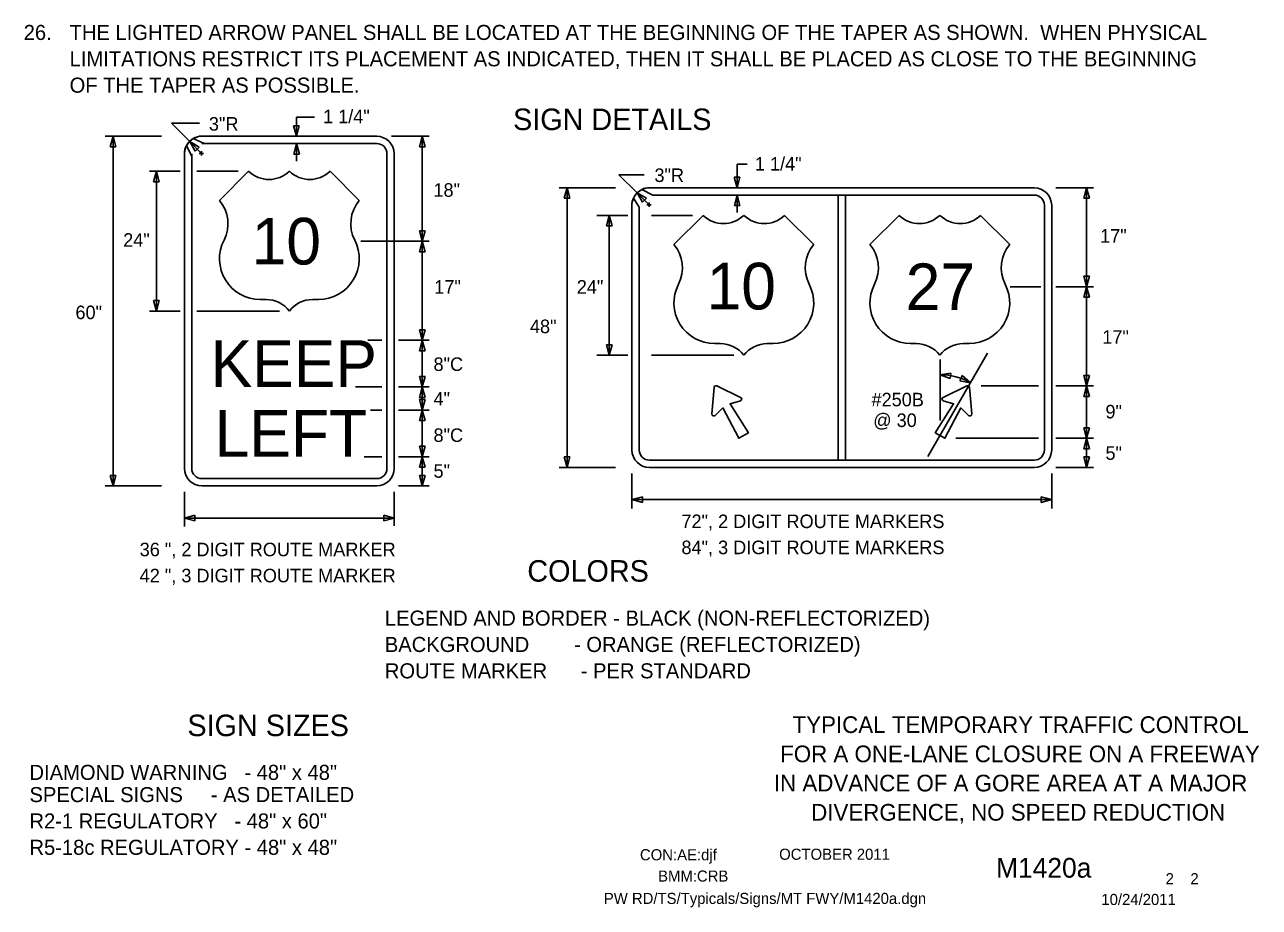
# Model space of a CAD drawing. Extents: x 16562 to 18475, y 6979 to 8243.
# Drawn here: x 17777 to 18465, y 7218 to 7710 of the extents above; entities that cross this region are included whole.
import ezdxf

# ---------------------------------------------------------------- set-up
doc = ezdxf.new("R2010")
doc.units = 0
for name, color, linetype in [('BORDER', 7, 'Continuous'), ('BORDER_SIGNAL_WO', 7, 'Continuous'), ('TRAFFIC_SIGNS_PR', 7, 'Continuous'), ('TYPICAL_EX', 7, 'Continuous'), ('TYPICAL_TEXT_DIMEN_PR', 7, 'Continuous')]:
    doc.layers.add(name, color=color, linetype=linetype)

msp = doc.modelspace()

# ---------------------------------------------------------------- linework, layer by layer
at = {"layer": 'TRAFFIC_SIGNS_PR'}
for p, q in [((17875.46, 7648.14), (17972.96, 7648.14)), ((17867.88, 7644.52), (17866.88, 7643.02)), ((17866.9, 7642.95), (17869.77, 7636.91)), ((17876.67, 7644.08), (17870.57, 7646.83)), ((17972.96, 7644.08), (17875.46, 7644.08)), ((17865.71, 7462.89), (17865.71, 7638.39)), ((17869.77, 7638.39), (17869.77, 7462.89)), ((17978.65, 7462.89), (17978.65, 7638.39)), ((17982.71, 7638.39), (17982.71, 7462.89)), ((18116.15, 7613.7), (18119.29, 7608.66)), ((18126.94, 7615.39), (18120.7, 7618.41)), ((18124.98, 7619.44), (18339.48, 7619.44)), ((18124.98, 7619.44), (18339.48, 7619.44)), ((18126.92, 7615.38), (18230.2, 7615.38)), ((18339.48, 7615.38), (18126.92, 7615.38)), ((18230.2, 7615.38), (18230.2, 7467.51)), ((18234.26, 7615.38), (18234.26, 7467.51)), ((18234.26, 7615.38), (18339.48, 7615.38)), ((18115.23, 7609.69), (18115.23, 7473.19)), ((18115.23, 7473.19), (18115.23, 7609.69)), ((18119.3, 7608.65), (18119.3, 7473.19)), ((18119.3, 7608.64), (18119.3, 7473.19)), ((18345.17, 7609.69), (18345.17, 7563.94)), ((18345.17, 7473.19), (18345.17, 7609.69)), ((18349.23, 7609.69), (18349.23, 7473.19)), ((18349.23, 7609.69), (18349.23, 7473.19)), ((18345.17, 7563.94), (18345.17, 7473.19)), ((18159.84, 7493.31), (18160.99, 7508.02)), ((18162.5, 7508.89), (18175.81, 7502.53)), ((18301.97, 7508.89), (18288.65, 7502.53)), ((18304.63, 7493.31), (18303.48, 7508.02)), ((18124.98, 7467.51), (18339.48, 7467.51)), ((18124.98, 7463.44), (18339.48, 7463.44)), ((18339.48, 7463.44), (18124.98, 7463.44)), ((17875.46, 7457.2), (17972.96, 7457.2)), ((17972.96, 7453.14), (17875.46, 7453.14))]:
    msp.add_line(p, q, dxfattribs=at)
for points in [[(18126.92, 7615.38), (18126.91, 7615.39)], [(18119.29, 7608.66), (18119.3, 7608.64)], [(18175.65, 7500.56), (18169.93, 7498.98), (18180.15, 7482.81), (18174.75, 7479.69), (18165.85, 7496.63), (18161.63, 7492.46)], [(18288.82, 7500.56), (18294.54, 7498.98), (18284.32, 7482.81), (18289.72, 7479.69), (18298.61, 7496.63), (18302.84, 7492.46)]]:
    msp.add_lwpolyline(points, dxfattribs=at)
msp.add_lwpolyline([(18230.2, 7615.38), (18234.26, 7615.38), (18234.26, 7467.51), (18230.2, 7467.51)], close=True, dxfattribs=at)
for centre, radius, start, end in [((17875.46, 7638.39), 9.75, 90, 180), ((17874.88, 7640.57), 7.6, 85.58319, 124.53531), ((17972.96, 7638.39), 9.75, 0, 90), ((17872.74, 7638.99), 7.06, 145.86811, 184.82317), ((17876.06, 7648.51), 4.47, 262.2432, 277.7568), ((17972.96, 7638.39), 5.69, 0, 90), ((17864.32, 7637.65), 5.51, 352.24294, 7.75653), ((18121.36, 7610.4), 6.17, 147.60925, 186.56283), ((18124.98, 7609.69), 9.75, 90, 180), ((18124.98, 7609.69), 9.75, 90, 180), ((18124.31, 7612.88), 6.6, 84.11162, 123.06374), ((18125.92, 7622.56), 7.24, 277.81035, 278.05403), ((18339.48, 7609.69), 9.75, 0, 90), ((18339.48, 7609.69), 9.75, 0, 90), ((18339.48, 7609.69), 5.69, 0, 89.99421), ((18339.48, 7609.69), 5.69, 0, 90), ((18162.04, 7507.94), 1.06, 64.48226, 175.51774), ((18302.42, 7507.94), 1.06, 4.48226, 115.51774), ((18175.36, 7501.58), 1.06, 285.9885, 64.48226), ((18289.11, 7501.58), 1.06, 115.51774, 254.0115), ((18160.89, 7493.22), 1.06, 175.51775, 314.01151), ((18303.58, 7493.22), 1.06, 225.98849, 4.48225), ((18124.98, 7473.19), 9.75, 180, 270), ((18124.98, 7473.19), 9.75, 180, 270), ((18124.98, 7473.19), 5.69, 180, 270), ((18124.98, 7473.19), 5.69, 180, 270), ((18339.48, 7473.19), 9.75, 270, 0), ((18339.48, 7473.19), 5.69, 270, 0), ((18339.48, 7473.19), 9.75, 270, 0), ((18339.48, 7473.19), 5.69, 270, 0), ((17875.46, 7462.89), 9.75, 180, 270), ((17875.46, 7462.89), 5.69, 180, 270), ((17972.96, 7462.89), 5.69, 270, 0), ((17972.96, 7462.89), 9.75, 270, 0)]:
    msp.add_arc(centre, radius, start, end, dxfattribs=at)
at = {"layer": 'TYPICAL_EX'}
for p, q in [((17885.21, 7612.4), (17901.46, 7628.65)), ((17963.21, 7612.4), (17946.96, 7628.65)), ((18138.59, 7587.79), (18154.84, 7604.04)), ((18216.6, 7587.79), (18200.34, 7604.04)), ((18247.87, 7587.79), (18264.12, 7604.04)), ((18325.88, 7587.79), (18309.62, 7604.04)), ((17907.94, 7557.1), (17911.19, 7557.1)), ((17940.48, 7557.1), (17937.23, 7557.1)), ((18161.32, 7532.49), (18164.57, 7532.49)), ((18193.87, 7532.49), (18190.62, 7532.49)), ((18270.6, 7532.49), (18273.85, 7532.49)), ((18303.15, 7532.49), (18299.9, 7532.49))]:
    msp.add_line(p, q, dxfattribs=at)
for centre, radius, start, end in [((17912.84, 7640.48), 16.42, 226.14041, 313.85958), ((17935.59, 7640.48), 16.42, 226.14042, 313.85959), ((17869.81, 7599.38), 20.16, 333.09768, 40.19361), ((17978.61, 7599.38), 20.16, 139.80639, 206.90233), ((18166.22, 7615.87), 16.42, 226.14041, 313.85958), ((18188.97, 7615.87), 16.42, 226.14042, 313.85959), ((18275.5, 7615.87), 16.42, 226.14041, 313.85958), ((18298.25, 7615.87), 16.42, 226.14042, 313.85959), ((17907.98, 7579.83), 22.73, 152.6698, 269.90132), ((17940.44, 7579.83), 22.73, 270.09868, 27.3302), ((18123.19, 7574.77), 20.16, 333.09768, 40.19361), ((18232, 7574.77), 20.16, 139.80639, 206.90233), ((18232.47, 7574.77), 20.16, 333.09768, 40.19361), ((18341.27, 7574.77), 20.16, 139.80639, 206.90233), ((18161.36, 7555.22), 22.73, 152.6698, 269.90132), ((18193.83, 7555.22), 22.73, 270.09868, 27.3302), ((18270.64, 7555.22), 22.73, 152.6698, 269.90132), ((18303.1, 7555.22), 22.73, 270.09868, 27.3302), ((17911.23, 7540.82), 16.28, 37.1038, 90.13853), ((17937.19, 7540.82), 16.28, 89.86147, 142.8962), ((18164.61, 7516.21), 16.28, 37.1038, 90.13853), ((18190.58, 7516.21), 16.28, 89.86147, 142.8962), ((18273.89, 7516.21), 16.28, 37.1038, 90.13853), ((18299.85, 7516.21), 16.28, 89.86147, 142.8962)]:
    msp.add_arc(centre, radius, start, end, dxfattribs=at)
at = {"layer": 'TYPICAL_TEXT_DIMEN_PR'}
for p, q in [((17874.08, 7655.43), (17858.42, 7655.43)), ((17858.42, 7655.43), (17868.66, 7645.19)), ((17928.18, 7658.9), (17928.18, 7648.14)), ((17928.18, 7658.9), (17938.29, 7658.9)), ((17852.88, 7648.14), (17821.59, 7648.14)), ((17824.35, 7642.28), (17825.93, 7648.14)), ((17825.93, 7648.14), (17825.93, 7453.14)), ((17825.93, 7648.14), (17827.5, 7642.28)), ((17928.18, 7648.14), (17926.61, 7654)), ((17926.61, 7654), (17928.18, 7654)), ((17928.18, 7654), (17929.75, 7654)), ((17929.75, 7654), (17928.18, 7648.14)), ((17981.25, 7648.14), (18002.21, 7648.14)), ((17996.74, 7642.28), (17998.31, 7648.14)), ((17998.31, 7648.14), (17998.31, 7589.64)), ((17998.31, 7648.14), (17999.89, 7642.28)), ((17825.93, 7642.28), (17824.35, 7642.28)), ((17827.5, 7642.28), (17825.93, 7642.28)), ((17868.66, 7645.19), (17875.22, 7638.63)), ((17871.7, 7639.94), (17868.66, 7645.19)), ((17868.66, 7645.19), (17873.92, 7642.16)), ((17872.81, 7641.05), (17871.7, 7639.94)), ((17873.92, 7642.16), (17872.81, 7641.05)), ((17926.66, 7638.22), (17928.23, 7644.08)), ((17928.23, 7644.08), (17928.23, 7634.33)), ((17928.23, 7644.08), (17929.8, 7638.22)), ((17998.31, 7642.28), (17996.74, 7642.28)), ((17999.89, 7642.28), (17998.31, 7642.28)), ((17874.01, 7638.63), (17876.43, 7638.63)), ((17875.22, 7637.42), (17875.22, 7639.84)), ((17928.23, 7638.22), (17926.66, 7638.22)), ((17929.8, 7638.22), (17928.23, 7638.22)), ((17863.34, 7628.64), (17846.21, 7628.64)), ((17848.54, 7622.78), (17850.11, 7628.64)), ((17850.11, 7628.64), (17850.11, 7550.64)), ((17850.11, 7628.64), (17851.68, 7622.78)), ((17895.58, 7628.64), (17872.7, 7628.64)), ((18173.84, 7632.6), (18173.84, 7619.44)), ((18173.84, 7632.6), (18179.37, 7632.6)), ((17850.11, 7622.78), (17848.54, 7622.78)), ((17851.68, 7622.78), (17850.11, 7622.78)), ((18122.12, 7626.73), (18107.95, 7626.73)), ((18107.95, 7626.73), (18118.1, 7616.58)), ((18173.84, 7619.44), (18172.27, 7625.31)), ((18172.27, 7625.31), (18173.84, 7625.31)), ((18173.84, 7625.31), (18175.41, 7625.31)), ((18175.41, 7625.31), (18173.84, 7619.44)), ((18106, 7619.44), (18074.71, 7619.44)), ((18077.47, 7613.58), (18079.05, 7619.44)), ((18079.05, 7613.58), (18077.47, 7613.58)), ((18079.05, 7619.44), (18079.05, 7463.44)), ((18079.05, 7619.44), (18080.62, 7613.58)), ((18080.62, 7613.58), (18079.05, 7613.58)), ((18118.1, 7616.58), (18124.74, 7609.94)), ((18121.13, 7611.32), (18118.1, 7616.58)), ((18118.1, 7616.58), (18123.35, 7613.55)), ((18123.35, 7613.55), (18122.24, 7612.44)), ((18172.32, 7609.52), (18173.89, 7615.38)), ((18172.32, 7609.52), (18173.89, 7615.38)), ((18173.89, 7615.38), (18173.89, 7605.63)), ((18173.89, 7615.38), (18175.46, 7609.52)), ((18173.89, 7615.38), (18175.46, 7609.52)), ((18351.61, 7619.44), (18372.56, 7619.44)), ((18367.1, 7613.58), (18368.67, 7619.44)), ((18368.67, 7613.58), (18367.1, 7613.58)), ((18368.67, 7619.44), (18368.67, 7564.19)), ((18368.67, 7619.44), (18370.24, 7613.58)), ((18370.24, 7613.58), (18368.67, 7613.58)), ((18122.24, 7612.44), (18121.13, 7611.32)), ((18123.53, 7609.94), (18125.95, 7609.94)), ((18124.74, 7608.73), (18124.74, 7611.15)), ((18173.89, 7609.52), (18172.32, 7609.52)), ((18173.89, 7609.52), (18172.32, 7609.52)), ((18175.46, 7609.52), (18173.89, 7609.52)), ((18175.46, 7609.52), (18173.89, 7609.52)), ((18112.86, 7604.03), (18095.73, 7604.03)), ((18101.03, 7598.17), (18102.6, 7604.03)), ((18102.6, 7604.03), (18102.6, 7526.03)), ((18102.6, 7604.03), (18104.17, 7598.17)), ((18148.96, 7604.03), (18126.08, 7604.03)), ((17998.31, 7589.64), (17996.74, 7595.5)), ((17996.74, 7595.5), (17998.31, 7595.5)), ((17998.31, 7595.5), (17999.89, 7595.5)), ((17999.89, 7595.5), (17998.31, 7589.64)), ((18102.6, 7598.17), (18101.03, 7598.17)), ((18104.17, 7598.17), (18102.6, 7598.17)), ((17964.1, 7589.64), (18002.21, 7589.64)), ((17996.74, 7583.78), (17998.31, 7589.64)), ((17998.31, 7589.64), (17998.31, 7534.39)), ((17998.31, 7589.64), (17999.89, 7583.78)), ((17998.31, 7583.78), (17996.74, 7583.78)), ((17999.89, 7583.78), (17998.31, 7583.78)), ((18368.67, 7564.19), (18367.1, 7570.06)), ((18367.1, 7570.06), (18368.67, 7570.06)), ((18368.67, 7570.06), (18370.24, 7570.06)), ((18370.24, 7570.06), (18368.67, 7564.19)), ((18326.05, 7564.19), (18343.2, 7564.19)), ((18351.61, 7564.19), (18372.56, 7564.19)), ((18367.1, 7558.33), (18368.67, 7564.19)), ((18368.67, 7558.33), (18367.1, 7558.33)), ((18368.67, 7564.19), (18368.67, 7508.94)), ((18368.67, 7564.19), (18370.24, 7558.33)), ((18370.24, 7558.33), (18368.67, 7558.33)), ((17850.11, 7550.64), (17848.54, 7556.5)), ((17848.54, 7556.5), (17850.11, 7556.5)), ((17850.11, 7556.5), (17851.68, 7556.5)), ((17851.68, 7556.5), (17850.11, 7550.64)), ((17863.34, 7550.64), (17846.21, 7550.64)), ((17918.7, 7550.64), (17872.7, 7550.64)), ((17998.31, 7534.39), (17996.74, 7540.25)), ((17996.74, 7540.25), (17998.31, 7540.25)), ((17998.31, 7540.25), (17999.89, 7540.25)), ((17999.89, 7540.25), (17998.31, 7534.39)), ((17968.04, 7534.39), (17975.72, 7534.39)), ((17985.08, 7534.39), (18002.21, 7534.39)), ((17996.74, 7528.53), (17998.31, 7534.39)), ((17998.31, 7534.39), (17998.31, 7508.39)), ((17998.31, 7534.39), (17999.89, 7528.53)), ((18102.6, 7526.03), (18101.03, 7531.89)), ((18101.03, 7531.89), (18102.6, 7531.89)), ((18102.6, 7531.89), (18104.17, 7531.89)), ((18104.17, 7531.89), (18102.6, 7526.03)), ((17998.31, 7528.53), (17996.74, 7528.53)), ((17999.89, 7528.53), (17998.31, 7528.53)), ((18112.86, 7526.03), (18095.73, 7526.03)), ((18172.08, 7526.03), (18126.08, 7526.03)), ((18280.26, 7469.54), (18313.5, 7527.13)), ((18287.02, 7489.7), (18287.02, 7523.69)), ((17998.31, 7508.39), (17996.74, 7514.25)), ((17996.74, 7514.25), (17998.31, 7514.25)), ((17998.31, 7514.25), (17999.89, 7514.25)), ((17999.89, 7514.25), (17998.31, 7508.39)), ((18287.05, 7515.14), (18293.04, 7516.1)), ((18292.72, 7512.97), (18287.05, 7515.14)), ((18292.88, 7514.53), (18292.72, 7512.97)), ((18293.04, 7516.1), (18292.88, 7514.53)), ((18298.04, 7511.81), (18298.72, 7513.23)), ((18304, 7510.68), (18298.04, 7511.81)), ((18298.72, 7513.23), (18299.4, 7514.64)), ((18299.4, 7514.64), (18304, 7510.68)), ((18368.67, 7508.94), (18367.1, 7514.81)), ((18367.1, 7514.81), (18368.67, 7514.81)), ((18368.67, 7514.81), (18370.24, 7514.81)), ((18370.24, 7514.81), (18368.67, 7508.94)), ((17961.02, 7508.39), (17975.72, 7508.39)), ((17985.08, 7508.39), (18002.21, 7508.39)), ((17996.74, 7502.53), (17998.31, 7508.39)), ((17998.31, 7508.39), (17998.31, 7495.39)), ((17998.31, 7508.39), (17999.89, 7502.53)), ((18309.97, 7508.94), (18341.84, 7508.94)), ((18351.61, 7508.94), (18372.56, 7508.94)), ((18367.1, 7503.08), (18368.67, 7508.94)), ((18368.67, 7503.08), (18367.1, 7503.08)), ((18368.67, 7508.94), (18368.67, 7479.69)), ((18368.67, 7508.94), (18370.24, 7503.08)), ((18370.24, 7503.08), (18368.67, 7503.08)), ((17998.31, 7502.53), (17996.74, 7502.53)), ((17998.31, 7495.39), (17996.74, 7501.25)), ((17996.74, 7501.25), (17998.31, 7501.25)), ((17999.89, 7502.53), (17998.31, 7502.53)), ((17998.31, 7501.25), (17999.89, 7501.25)), ((17999.89, 7501.25), (17998.31, 7495.39)), ((17969.38, 7495.39), (17975.72, 7495.39)), ((17985.08, 7495.39), (18002.21, 7495.39)), ((17996.74, 7489.53), (17998.31, 7495.39)), ((17998.31, 7489.53), (17996.74, 7489.53)), ((17998.31, 7495.39), (17998.31, 7469.39)), ((17998.31, 7495.39), (17999.89, 7489.53)), ((17999.89, 7489.53), (17998.31, 7489.53)), ((18368.67, 7479.69), (18367.1, 7485.56)), ((18367.1, 7485.56), (18368.67, 7485.56)), ((18368.67, 7485.56), (18370.24, 7485.56)), ((18370.24, 7485.56), (18368.67, 7479.69)), ((18295.84, 7479.69), (18341.84, 7479.69)), ((18351.61, 7479.69), (18372.56, 7479.69)), ((18367.1, 7473.83), (18368.67, 7479.69)), ((18368.67, 7479.69), (18368.67, 7463.44)), ((18368.67, 7479.69), (18370.24, 7473.83)), ((17965.88, 7469.39), (17975.72, 7469.39)), ((17985.08, 7469.39), (18002.21, 7469.39)), ((17998.31, 7469.39), (17996.74, 7475.25)), ((17996.74, 7475.25), (17998.31, 7475.25)), ((17996.74, 7463.53), (17998.31, 7469.39)), ((17998.31, 7475.25), (17999.89, 7475.25)), ((17999.89, 7475.25), (17998.31, 7469.39)), ((17998.31, 7469.39), (17998.31, 7453.14)), ((17998.31, 7469.39), (17999.89, 7463.53)), ((18079.05, 7463.44), (18077.47, 7469.31)), ((18077.47, 7469.31), (18079.05, 7469.31)), ((18079.05, 7469.31), (18080.62, 7469.31)), ((18080.62, 7469.31), (18079.05, 7463.44)), ((18368.67, 7473.83), (18367.1, 7473.83)), ((18368.67, 7463.44), (18367.1, 7469.31)), ((18367.1, 7469.31), (18368.67, 7469.31)), ((18370.24, 7473.83), (18368.67, 7473.83)), ((18368.67, 7469.31), (18370.24, 7469.31)), ((18370.24, 7469.31), (18368.67, 7463.44)), ((17998.31, 7463.53), (17996.74, 7463.53)), ((17999.89, 7463.53), (17998.31, 7463.53)), ((18106, 7463.44), (18074.71, 7463.44)), ((18351.61, 7463.44), (18368.73, 7463.44)), ((18351.61, 7463.44), (18372.56, 7463.44)), ((18351.61, 7463.44), (18368.73, 7463.44)), ((17825.93, 7453.14), (17824.35, 7459)), ((17824.35, 7459), (17825.93, 7459)), ((17825.93, 7459), (17827.5, 7459)), ((17827.5, 7459), (17825.93, 7453.14)), ((17998.31, 7453.14), (17996.74, 7459)), ((17996.74, 7459), (17998.31, 7459)), ((17998.31, 7459), (17999.89, 7459)), ((17999.89, 7459), (17998.31, 7453.14)), ((18115.23, 7460.1), (18115.23, 7440.54)), ((18349.23, 7460.1), (18349.23, 7440.54)), ((17852.88, 7453.14), (17821.59, 7453.14)), ((17865.71, 7449.8), (17865.71, 7430.45)), ((17982.71, 7449.8), (17982.71, 7430.9)), ((17985.08, 7453.14), (18002.21, 7453.14)), ((18115.23, 7445.47), (18121.1, 7447.04)), ((18115.23, 7445.47), (18349.23, 7445.47)), ((18121.1, 7443.9), (18115.23, 7445.47)), ((18121.1, 7447.04), (18121.1, 7445.47)), ((18121.1, 7445.47), (18121.1, 7443.9)), ((18343.37, 7445.47), (18343.37, 7447.04)), ((18343.37, 7447.04), (18349.23, 7445.47)), ((18349.23, 7445.47), (18343.37, 7443.9)), ((18343.37, 7443.9), (18343.37, 7445.47)), ((17865.71, 7435.17), (17871.57, 7436.74)), ((17865.71, 7435.17), (17982.71, 7435.17)), ((17871.57, 7433.6), (17865.71, 7435.17)), ((17871.57, 7436.74), (17871.57, 7435.17)), ((17871.57, 7435.17), (17871.57, 7433.6)), ((17976.85, 7435.17), (17976.85, 7436.74)), ((17976.85, 7436.74), (17982.71, 7435.17)), ((17982.71, 7435.17), (17976.85, 7433.6)), ((17976.85, 7433.6), (17976.85, 7435.17))]:
    msp.add_line(p, q, dxfattribs=at)
msp.add_arc((18287.21, 7480.7), 34.39, 60.74521, 90.32117, dxfattribs=at)

# ---------------------------------------------------------------- texts
at = {"layer": 'BORDER'}
for s, p in [('TYPICAL TEMPORARY TRAFFIC CONTROL', (18204.79, 7315.33)), ('FOR A ONE-LANE CLOSURE ON A FREEWAY', (18197.85, 7299.03)), ('IN ADVANCE OF A GORE AREA AT A MAJOR', (18194.35, 7282.73)), ('DIVERGENCE, NO SPEED REDUCTION', (18215.16, 7266.43))]:
    msp.add_text(s, height=9.3, dxfattribs=at).set_placement(p)
at = {"layer": 'BORDER_SIGNAL_WO'}
for s, height, p in [('CON:AE:djf  ', 6.2, (18119.69, 7244.31)), ('    OCTOBER 2011    ', 6.2, (18188.08, 7244.59)), ('    M1420a   ', 11, (18301.86, 7234.63)), ('BMM:CRB   ', 6.2, (18129.81, 7232.42)), (' 2    2 ', 6.2, (18410.45, 7230.95)), ('PW RD/TS/Typicals/Signs/MT FWY/M1420a.dgn      ', 6.2, (18099.55, 7219.96)), ('10/24/2011    ', 6.2, (18376.93, 7219.38))]:
    msp.add_text(s, height=height, dxfattribs=at).set_placement(p)
at = {"layer": 'TRAFFIC_SIGNS_PR'}
for s, p in [('10', (17903.18, 7576.64)), ('10', (18156.83, 7551.57)), ('27', (18267.84, 7551.21)), ('KEEP', (17880.31, 7508.39)), ('LEFT', (17882.55, 7469.39))]:
    msp.add_text(s, height=26, dxfattribs=at).set_placement(p)
at = {"layer": 'TYPICAL_TEXT_DIMEN_PR'}
for s, height, p in [('26.', 8.4, (17776.09, 7701.87)), ('THE LIGHTED ARROW PANEL SHALL BE LOCATED AT THE BEGINNING OF THE TAPER AS SHOWN.  WHEN PHYSICAL', 8.4, (17801.7, 7701.87)), ('LIMITATIONS RESTRICT ITS PLACEMENT AS INDICATED, THEN IT SHALL BE PLACED AS CLOSE TO THE BEGINNING', 8.4, (17801.7, 7687.17)), ('OF THE TAPER AS POSSIBLE.', 8.4, (17801.7, 7672.47)), ('1 1/4"', 7.55, (17942.99, 7655.4)), ('SIGN DETAILS', 12, (18048.94, 7651.61)), ('3"R', 7.55, (17879.35, 7651.3)), ('1 1/4"', 7.55, (18183.77, 7629.02)), ('3"R', 7.55, (18127.76, 7622.65)), ('18"', 7.55, (18004.55, 7614.41)), ('24"', 7.55, (17831.56, 7586.53)), ('17"', 7.55, (18376.24, 7588.8)), ('17"', 7.55, (18005.01, 7560.36)), ('24"', 7.55, (18084.46, 7560.36)), ('60"', 7.55, (17804.95, 7546.16)), ('48"', 7.55, (18058.34, 7538.34)), ('17"', 7.55, (18377.45, 7532.44)), ('8"C', 7.55, (18004.59, 7517.25)), ('4" ', 7.55, (18004.59, 7497.99)), ('#250B', 7.55, (18248.79, 7497.53)), ('9"', 7.55, (18379.22, 7490.79)), ('@ 30', 7.55, (18249.74, 7485.99)), ('8"C', 7.55, (18004.59, 7477.66)), ('5"', 7.55, (18379.22, 7467.69)), ('5" ', 7.55, (18004.59, 7457.69)), ('72", 2 DIGIT ROUTE MARKERS', 7.55, (18142.81, 7429.61)), ('36 ", 2 DIGIT ROUTE MARKER', 7.55, (17840.76, 7413.91)), ('84", 3 DIGIT ROUTE MARKERS', 7.55, (18142.81, 7415.06)), ('42 ", 3 DIGIT ROUTE MARKER', 7.55, (17840.76, 7399.36)), ('COLORS', 12, (18056.88, 7399.73)), ('LEGEND AND BORDER - BLACK (NON-REFLECTORIZED)', 8.4, (17977.45, 7375.2)), ('BACKGROUND        - ORANGE (REFLECTORIZED)', 8.4, (17977.45, 7360.5)), ('ROUTE MARKER      - PER STANDARD', 8.4, (17977.45, 7345.8)), ('SIGN SIZES', 12, (17867.36, 7313.56)), ('DIAMOND WARNING   - 48" x 48"', 8.4, (17779.32, 7289.16)), ('SPECIAL SIGNS     - AS DETAILED', 8.4, (17779.32, 7276.76)), ('R2-1 REGULATORY   - 48" x 60"', 8.4, (17779.32, 7262.06)), ('R5-18c REGULATORY - 48" x 48"', 8.4, (17779.32, 7247.36))]:
    msp.add_text(s, height=height, dxfattribs=at).set_placement(p)

doc.saveas('drawing.dxf')
